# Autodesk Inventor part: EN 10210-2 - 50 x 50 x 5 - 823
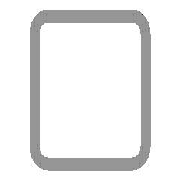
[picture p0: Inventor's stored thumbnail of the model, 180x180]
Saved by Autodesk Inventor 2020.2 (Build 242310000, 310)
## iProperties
_CCFamilyMember: 16
_CCFamilyDisplayName: DIN EN 10210-2 (USAS B17.1 quadratisch) - Rohrleitung — In Klammern angegebene Größen wurden aufgehoben
_FrameMemberDoc: Frame Member File
_Version: 15.0.0
_GetPNFromCC: 1
IsCustomPart: 1
Created: 2019-01
Part Number: EN 10210-2 - 50 x 50 x 5 - 823
Material: Stahl, weich
Description: Rohrleitung
Document SubType Name: Modeling
Standard: DIN
Designer: lutzd
Standard Revision: 2006-07
Standards Organization: DIN
Language: de-DE
Size Designation: 50 x 50 x 5
Categories: <MemberInstance><Categories><Category DisplayName="Profile" InternalName="089c4875-fa83-4c05-b084-43b9cc11f5ed" Mnemonic="GRDR"><CategoryParameter DisplayName="
Stock Number: 50 x 50 x 5
Mass: 5641.19 g
Surface Area: 2803.65 cm^2
Volume: 718.623 cm^3
Density: 7.85 g/cm^3
Appearance: Semi-Polished(8)
G_L: 823,000 mm
G_W: 50,000 mm
G_H: 50,000 mm
DocNumber: ADSK-014275
Folder: .
Dimensions: 50x50x823 mm
Mass: 5,641 kg
+3773E351-B0CA-44AC-91BD-2F4C67E6A7B3+SCHNITTDETAIL1: Schnittwinkel 90,00 grd
+802290EE-AC2C-4BE2-B048-E9041E20CD25+SCHNITTDETAIL2: Schnittwinkel 90,00 grd
VLT_Material: Stahl, weich
Title: Profil-Bauteil
Author: lutzd
Revision Number: -
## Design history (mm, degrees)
node "Startebene"
node "Endebene"
sketch "Skizze"
  geometry: L1 (-25, -17.5)-(-25, 17.5); L2 (-17.5, 25)-(17.5, 25); L3 (25, 17.5)-(25, -17.5); L4 (17.5, -25)-(-17.5, -25); L5 (-15, 20)-(15, 20); L6 (20, 15)-(20, -15); L7 (15, -20)-(-15, -20); L8 (-20, -15)-(-20, 15); L9 (0, 37.175)-(0, -37.175) reference; L10 (-37.175, 0)-(37.175, 0) reference; A1 r 7.5 centre (-17.5, -17.5) between (-25, -17.5) and (-17.5, -25); A2 r 7.5 centre (-17.5, 17.5) between (-17.5, 25) and (-25, 17.5); A3 r 7.5 centre (17.5, 17.5) between (25, 17.5) and (17.5, 25); A4 r 7.5 centre (17.5, -17.5) between (17.5, -25) and (25, -17.5); A5 r 5 centre (-15, -15) between (-20, -15) and (-15, -20); A6 r 5 centre (-15, 15) between (-15, 20) and (-20, 15); A7 r 5 centre (15, 15) between (20, 15) and (15, 20); A8 r 5 centre (15, -15) between (15, -20) and (20, -15)
  constraints: 16 end point, 16 point on circle, 16 tangent, 8 centre point, 6 equal radius, 4 parallel, 2 perpendicular, 2 other
  dimensions: "d7" = 7.5 radius of A1 (= G_IR); "d10" = 50 distance between parallel lines of L2 L4 (= G_H); "d11" = 50 distance between parallel lines of L1 L3 (= G_W); "d12" = 5 distance between parallel lines of L3 L6 (= G_T); "d15" = 25 distance between parallel lines of L2 L10 (= 0.5 x d10); "d16" = 25 distance between parallel lines of L9 L3 (= 0.5 x d11); "d19" = 5 radius of A5 (= G_T); "d20" = 5 distance between parallel lines of L4 L7 (= G_T)
extrude "Körper" new body sketch "Skizze" stored distance "d3" = 823 (= G_L); taper "d4" = 0 deg
node "Driven Length"
  sketch "Sketch3"
    geometry: L1 (0, 0)-(10, 0) reference
    constraints: 2 end point, 1 horizontal
  workplane "Work Plane3"
  sketch "Sketch4"
    geometry: L1 (-2, 35)-(12, 35) reference; L2 (-2, 858)-(12, 858) reference
    dimensions: "d18" = 823 distance between parallel lines of L1 L2 (derived)
workplane "Arbeitsebene4"
feature "Trennen1"
workplane "Arbeitsebene5"
feature "Trennen2"
body "Solid1"
other parameters: "G_W" = 50 [user parameter; used in 1 equation term], "G_H" = 50 [user parameter; used in 1 equation term], "G_T" = 5 [user parameter; used in 3 equation terms], "G_IR" = 7.5 [user parameter; used in 1 equation term], "G_L" = 823 (= d18) [user parameter; used in 1 equation term], "G_OFFSET_START" = -35 [user parameter; used in 1 equation term], "d13" = 35 (= -G_OFFSET_START), "d14" = 858 (= G_OFFSET_END + B_L), "B_L" = 908 [user parameter; used in 1 equation term], "d17" = 90 deg
